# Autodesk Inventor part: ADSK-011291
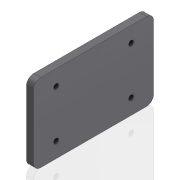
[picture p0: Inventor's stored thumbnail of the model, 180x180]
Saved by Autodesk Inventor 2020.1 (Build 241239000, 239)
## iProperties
Created: 1999-11
Part Number: ADSK-011291
Material: Acier doux
Document SubType Name: Modeling
Designer: sspink
Density: 7.86 g/cm^3
Appearance: Metal-Steel(Polish)
Mass: 312.247 g
Surface Area: 155.031 cm^2
Volume: 39.726 cm^3
Control State: 0
Checked Out: False
Last Check In By: sspink
Last Check In Date: 1999-12-16
Master: False
Shininess: 0.0
Length Units: 11269
Angle Units: 11279
Time Units: 11290
Mass Units: 11283
Length Display Precision: 3
Angle Display Precision: 2
Compacted: True
Dimensions: 6x66x101,6 mm
Mass: 0,312 kg
DocNumber: ADSK-011291.ipt
Folder: 01 - Themengebiete\Simplification\01 - Packaging machine\
VDS_Category: 3D Komponenten
Density: 0.0
Volumn: 0.0
Area: 0.0
PropertySet Name: Model Information
Author: sspink
Revision Number: -
Title: plate
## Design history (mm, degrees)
node "Solide1"
  node "Extrusion1" dims "d0" = 101.6, "d1" = 0
  node "Fillet1" dims "d2" = 6
sketch "Sketch1"
  geometry: L1 (-3, -33)-(3, -33); L2 (3, -33)-(3, 33); L3 (-3, -33)-(-3, 33); L4 (-3, 33)-(3, 33); 3 further points
  constraints: 8 end point, 2 midpoint, 2 perpendicular, 1 horizontal alignment, 1 parallel, 1 vertical, 1 vertical alignment
  dimensions: "d17" = 6 distance of L3.end L2.end; "d18" = 66 distance of L1.start L3.end
sketch "Sketch2"
  geometry: L1 (-19.05, 178.437)-(-82.55, 178.437); L2 (-6, 165.437)-(-95.6, 165.437) reference; L3 (-101.6, 171.437)-(-101.6, 225.437) reference; L4 (-82.55, 178.437)-(-82.55, 218.437); L5 (-82.55, 218.437)-(-19.05, 218.437); L6 (-19.05, 218.437)-(-19.05, 178.437); L7 (-95.6, 231.437)-(-6, 231.437) reference; L8 (0, 225.437)-(0, 171.437) reference; 6 further points
  constraints: 8 end point, 4 midpoint, 2 coincident, 2 perpendicular, 1 horizontal, 1 horizontal alignment, 1 vertical, 1 vertical alignment
  dimensions: "d22" = 40 distance of L5.end L1.start; "d23" = 63.5 distance of L1.start L1.end
hole "Bohrung2" sketch "Sketch2" diameter "d24" = 4.134; stored, may be unused: countersink angle "d28" = 90 deg, drill point angle "d30" = 118 deg; dims "d25" = 10, "d26" = 19, "d27" = 2, "d29" = 14.2
node "Corps solides"
node "Corps surfaciques"
